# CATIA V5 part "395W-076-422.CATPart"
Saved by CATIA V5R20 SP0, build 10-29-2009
Part number: 395W-076-422
Bounding box of the stored display mesh (mm): x -15 to 407, y -47.5 to 47.5, z -47.5 to 47.5
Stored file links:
  C:\Users\Raffaele\Desktop\3D X SITO CF\PERNI -STAFFE SOLLEVAMENTO\395W\395W-076-422.CATPart
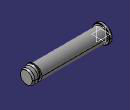
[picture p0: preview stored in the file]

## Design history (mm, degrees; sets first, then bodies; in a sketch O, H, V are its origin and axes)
Body1 (main body)
  Solid1 "ImportedBody": solid without history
